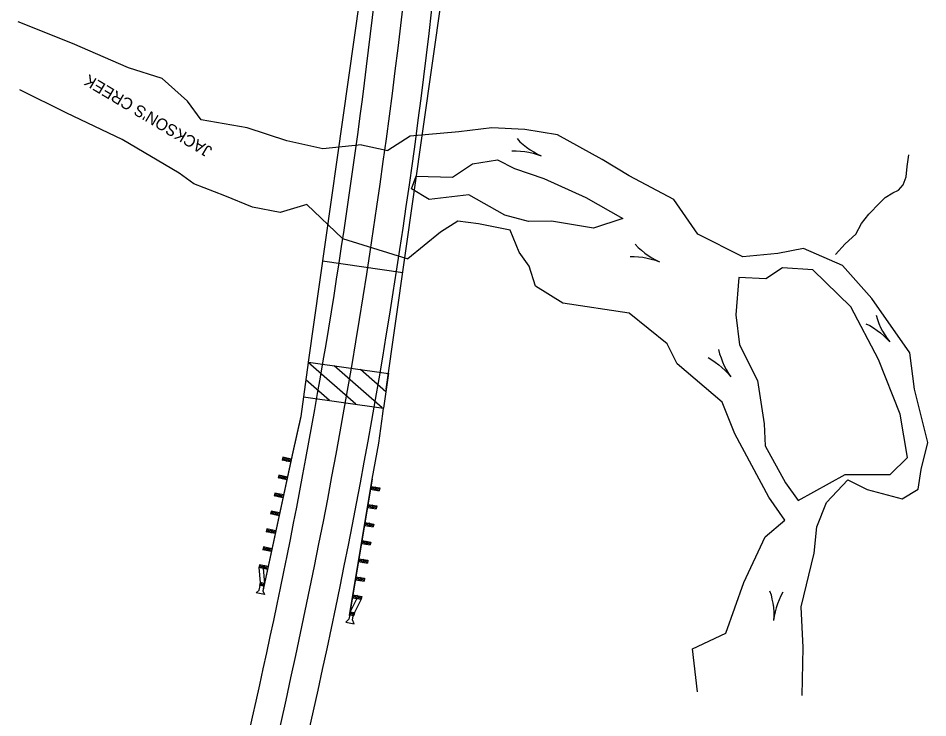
# Model space of a CAD drawing. Extents: x 1698609 to 1700392, y 707479 to 710040.
# Drawn here: x 1699277.7 to 1699590.3, y 708555.6 to 708796 of the extents above; entities that cross this region are included whole.
import ezdxf

# ---------------------------------------------------------------- set-up
doc = ezdxf.new("R2010")
doc.units = 0
for name, color, linetype in [('Default', 7, 'Continuous'), ('Exist Hydro Jurisdictional Stream or Body of Water', 7, 'Continuous'), ('Exist Hydro Jurisdictional Stream or Body of Water Text', 7, 'Continuous'), ('Exist Hydro Stream Flow Arrow CELL', 7, 'Continuous'), ('Exist Hydro Stream or Body of Water', 7, 'Continuous'), ('Prop Horizontal Alignment', 7, 'Continuous')]:
    doc.layers.add(name, color=color, linetype=linetype)

# ---------------------------------------------------------------- blocks, each defined once
blk = doc.blocks.new('EXIST HYDRO STREAM FLOW ARROW')
at = {"layer": 'Exist Hydro Stream Flow Arrow CELL'}
blk.add_line((0, 0), (0, 0), dxfattribs=at)
for points in [[(-0.1, 0.04575), (-0.07325, 0.03375), (-0.04475, 0.0245), (-0.0165, 0.01575), (0.01175, 0.0095), (0.041, 0.00475), (0.07075, 0.0015), (0.1, 0)], [(-0.1, -0.04575), (-0.07325, -0.03375), (-0.04475, -0.0245), (-0.0165, -0.01575), (0.01175, -0.0095), (0.041, -0.00475), (0.07075, -0.0015), (0.1, 0)]]:
    blk.add_lwpolyline(points, dxfattribs=at)

msp = doc.modelspace()

# ---------------------------------------------------------------- linework, layer by layer
at = {"layer": 'Default'}
for p, q in [((1699377.38, 708677.82), (1699397.03, 708816.44)), ((1699404.18, 708668.57), (1699424.59, 708812.53)), ((1699409.85, 708708.57), (1699382.3, 708712.47)), ((1699377.37, 708677.75), (1699375.7, 708665.94)), ((1699393.66, 708663.39), (1699377.36, 708677.67)), ((1699377.38, 708677.82), (1699404.94, 708673.92)), ((1699402.72, 708662.11), (1699386.21, 708676.57)), ((1699404.05, 708667.59), (1699395.26, 708675.29)), ((1699404.95, 708673.99), (1699403.26, 708662.03)), ((1699384.61, 708664.68), (1699376.52, 708671.76)), ((1699375.73, 708665.94), (1699374.79, 708659.14)), ((1699375.7, 708665.94), (1699403.26, 708662.03)), ((1699402.98, 708660.05), (1699403.26, 708662.03)), ((1699374.75, 708659.26), (1699372.04, 708647.01)), ((1699374.79, 708659.14), (1699372.08, 708646.9)), ((1699401.55, 708650.01), (1699402.98, 708660.05)), ((1699399.36, 708637.66), (1699401.55, 708650.01)), ((1699399.36, 708637.66), (1699401.55, 708650.01)), ((1699372.08, 708646.9), (1699361.75, 708599.17)), ((1699372.04, 708647.01), (1699362.19, 708601.31)), ((1699368.57, 708645.16), (1699368.36, 708644.18)), ((1699371.51, 708644.53), (1699368.57, 708645.16)), ((1699369.83, 708643.87), (1699368.57, 708645.16)), ((1699368.36, 708644.18), (1699370.04, 708644.85)), ((1699371.29, 708643.55), (1699368.36, 708644.18)), ((1699370.04, 708644.85), (1699369.83, 708643.87)), ((1699369.83, 708643.87), (1699371.51, 708644.53)), ((1699371.29, 708643.55), (1699369.83, 708643.87)), ((1699370.04, 708644.85), (1699371.29, 708643.55)), ((1699371.51, 708644.53), (1699371.29, 708643.55)), ((1699367.19, 708639.01), (1699366.98, 708638.04)), ((1699366.98, 708638.04), (1699368.69, 708638.69)), ((1699370.18, 708638.37), (1699367.19, 708639.01)), ((1699368.47, 708637.71), (1699367.19, 708639.01)), ((1699368.69, 708638.69), (1699368.47, 708637.71)), ((1699368.69, 708638.69), (1699369.97, 708637.39)), ((1699369.97, 708637.39), (1699366.98, 708638.04)), ((1699370.18, 708638.37), (1699368.47, 708637.71)), ((1699391.51, 708590.84), (1699399.36, 708637.66)), ((1699399.36, 708637.66), (1699391.63, 708591.55)), ((1699365.87, 708632.85), (1699365.66, 708631.87)), ((1699365.66, 708631.87), (1699367.36, 708632.53)), ((1699368.85, 708632.21), (1699365.87, 708632.85)), ((1699367.15, 708631.55), (1699365.87, 708632.85)), ((1699367.36, 708632.53), (1699367.15, 708631.55)), ((1699367.36, 708632.53), (1699368.64, 708631.23)), ((1699398.94, 708635.15), (1699398.77, 708634.17)), ((1699400.42, 708634.91), (1699398.77, 708634.17)), ((1699398.77, 708634.17), (1699401.73, 708633.67)), ((1699398.77, 708634.17), (1699400.25, 708633.92)), ((1699398.94, 708635.15), (1699401.9, 708634.66)), ((1699400.25, 708633.92), (1699398.94, 708635.15)), ((1699400.42, 708634.91), (1699400.25, 708633.92)), ((1699400.25, 708633.92), (1699401.9, 708634.66)), ((1699401.73, 708633.67), (1699400.42, 708634.91)), ((1699401.9, 708634.66), (1699401.73, 708633.67)), ((1699368.64, 708631.23), (1699365.66, 708631.87)), ((1699368.85, 708632.21), (1699367.15, 708631.55)), ((1699364.55, 708626.69), (1699364.34, 708625.71)), ((1699364.34, 708625.71), (1699366.04, 708626.37)), ((1699367.52, 708626.05), (1699364.55, 708626.69)), ((1699365.83, 708625.39), (1699364.55, 708626.69)), ((1699366.04, 708626.37), (1699365.83, 708625.39)), ((1699366.04, 708626.37), (1699367.31, 708625.07)), ((1699399.4, 708628.69), (1699397.73, 708627.95)), ((1699397.73, 708627.95), (1699400.74, 708627.45)), ((1699397.9, 708628.94), (1699400.91, 708628.43)), ((1699397.9, 708628.94), (1699399.24, 708627.7)), ((1699399.4, 708628.69), (1699399.24, 708627.7)), ((1699399.24, 708627.7), (1699400.91, 708628.43)), ((1699400.74, 708627.45), (1699399.4, 708628.69)), ((1699400.91, 708628.43), (1699400.74, 708627.45)), ((1699367.31, 708625.07), (1699364.34, 708625.71)), ((1699367.52, 708626.05), (1699365.83, 708625.39)), ((1699367.52, 708626.05), (1699367.31, 708625.07)), ((1699363.13, 708620.55), (1699362.92, 708619.57)), ((1699362.92, 708619.57), (1699364.66, 708620.22)), ((1699366.19, 708619.89), (1699363.13, 708620.55)), ((1699364.45, 708619.24), (1699363.13, 708620.55)), ((1699364.66, 708620.22), (1699364.45, 708619.24)), ((1699366.19, 708619.89), (1699364.45, 708619.24)), ((1699364.66, 708620.22), (1699365.98, 708618.91)), ((1699398.36, 708622.47), (1699396.69, 708621.74)), ((1699396.69, 708621.74), (1699399.7, 708621.23)), ((1699396.86, 708622.72), (1699399.86, 708622.22)), ((1699396.86, 708622.72), (1699398.19, 708621.49)), ((1699398.36, 708622.47), (1699398.19, 708621.49)), ((1699398.19, 708621.49), (1699399.86, 708622.22)), ((1699399.7, 708621.23), (1699398.36, 708622.47)), ((1699399.86, 708622.22), (1699399.7, 708621.23)), ((1699365.98, 708618.91), (1699362.92, 708619.57)), ((1699361.93, 708614.36), (1699361.72, 708613.38)), ((1699361.72, 708613.38), (1699363.4, 708614.05)), ((1699364.87, 708613.73), (1699361.93, 708614.36)), ((1699363.19, 708613.07), (1699361.93, 708614.36)), ((1699363.4, 708614.05), (1699363.19, 708613.07)), ((1699364.87, 708613.73), (1699363.19, 708613.07)), ((1699363.4, 708614.05), (1699364.65, 708612.75)), ((1699395.82, 708616.51), (1699395.65, 708615.52)), ((1699397.31, 708616.26), (1699395.65, 708615.52)), ((1699395.65, 708615.52), (1699398.64, 708615.02)), ((1699395.82, 708616.51), (1699398.81, 708616.01)), ((1699395.82, 708616.51), (1699397.15, 708615.27)), ((1699397.31, 708616.26), (1699397.15, 708615.27)), ((1699397.15, 708615.27), (1699398.81, 708616.01)), ((1699398.64, 708615.02), (1699397.31, 708616.26)), ((1699398.81, 708616.01), (1699398.64, 708615.02)), ((1699364.65, 708612.75), (1699361.72, 708613.38)), ((1699360.54, 708608.22), (1699360.33, 708607.24)), ((1699360.33, 708607.24), (1699362.04, 708607.89)), ((1699363.54, 708607.57), (1699360.54, 708608.22)), ((1699361.83, 708606.92), (1699360.54, 708608.22)), ((1699362.04, 708607.89), (1699361.83, 708606.92)), ((1699363.54, 708607.57), (1699361.83, 708606.92)), ((1699362.04, 708607.89), (1699363.33, 708606.59)), ((1699396.32, 708610.04), (1699394.61, 708609.31)), ((1699394.61, 708609.31), (1699397.7, 708608.79)), ((1699394.77, 708610.3), (1699397.87, 708609.78)), ((1699394.77, 708610.3), (1699396.16, 708609.05)), ((1699396.32, 708610.04), (1699396.16, 708609.05)), ((1699396.16, 708609.05), (1699397.87, 708609.78)), ((1699397.7, 708608.79), (1699396.32, 708610.04)), ((1699397.87, 708609.78), (1699397.7, 708608.79)), ((1699363.33, 708606.59), (1699360.33, 708607.24)), ((1699360.33, 708607.24), (1699360.83, 708602.12)), ((1699361.83, 708606.92), (1699362.29, 708601.8)), ((1699360.51, 708599.53), (1699360.91, 708601.53)), ((1699360.83, 708602.12), (1699360.62, 708601.14)), ((1699360.62, 708601.14), (1699362.29, 708601.8)), ((1699362.08, 708600.82), (1699360.62, 708601.14)), ((1699360.83, 708602.12), (1699360.72, 708601.63)), ((1699362.29, 708601.8), (1699360.83, 708602.12)), ((1699362.08, 708600.82), (1699360.83, 708602.12)), ((1699360.91, 708601.53), (1699361.51, 708601.42)), ((1699361.51, 708601.42), (1699362.11, 708601.3)), ((1699362.11, 708601.3), (1699361.71, 708599.29)), ((1699395.21, 708603.83), (1699393.57, 708603.09)), ((1699393.57, 708603.09), (1699396.53, 708602.6)), ((1699393.73, 708604.08), (1699396.69, 708603.59)), ((1699393.73, 708604.08), (1699395.05, 708602.85)), ((1699395.21, 708603.83), (1699395.05, 708602.85)), ((1699395.05, 708602.85), (1699396.69, 708603.59)), ((1699396.53, 708602.6), (1699395.21, 708603.83)), ((1699396.69, 708603.59), (1699396.53, 708602.6)), ((1699359.45, 708598.54), (1699360.51, 708599.53)), ((1699362.33, 708597.97), (1699359.45, 708598.54)), ((1699361.71, 708599.29), (1699362.33, 708597.97)), ((1699394.04, 708596.63), (1699391.72, 708592.05)), ((1699394.2, 708597.61), (1699392.53, 708596.88)), ((1699392.53, 708596.88), (1699395.55, 708596.37)), ((1699392.69, 708597.87), (1699395.71, 708597.36)), ((1699392.69, 708597.87), (1699394.04, 708596.63)), ((1699395.55, 708596.37), (1699393.19, 708591.8)), ((1699394.2, 708597.61), (1699394.04, 708596.63)), ((1699394.04, 708596.63), (1699395.71, 708597.36)), ((1699395.55, 708596.37), (1699394.2, 708597.61)), ((1699395.71, 708597.36), (1699395.55, 708596.37)), ((1699391.55, 708591.06), (1699393.19, 708591.8)), ((1699391.72, 708592.05), (1699393.19, 708591.8)), ((1699393.03, 708590.81), (1699391.72, 708592.05)), ((1699393.19, 708591.8), (1699393.03, 708590.81)), ((1699393.19, 708591.8), (1699393.11, 708591.31)), ((1699391.33, 708589.5), (1699390.26, 708588.5)), ((1699391.7, 708591.51), (1699391.33, 708589.5)), ((1699391.55, 708591.06), (1699393.03, 708590.81)), ((1699392.3, 708591.4), (1699391.7, 708591.51)), ((1699392.9, 708591.29), (1699392.3, 708591.4)), ((1699392.53, 708589.27), (1699392.9, 708591.29)), ((1699393.15, 708587.96), (1699392.53, 708589.27)), ((1699390.26, 708588.5), (1699393.15, 708587.96))]:
    msp.add_line(p, q, dxfattribs=at)
for centre, radius, start, end in [((1697124.94, 709062.69), 2310, 350.26654, 356.20849), ((1697132.82, 709061.2), 2282.04, 344.49766, 353.61848), ((1697124.94, 709062.69), 2310, 344.49666, 350.26654)]:
    msp.add_arc(centre, radius, start, end, dxfattribs=at)
at = {"layer": 'Exist Hydro Jurisdictional Stream or Body of Water'}
for p, q in [((1699395.69, 708752.5), (1699404.74, 708750.56)), ((1699412.8, 708737.33), (1699414.38, 708741.71)), ((1699389.13, 708720.33), (1699411.61, 708713.36)), ((1699525.28, 708706.88), (1699524.31, 708694.13)), ((1699541.4, 708636.34), (1699545.67, 708630.32))]:
    msp.add_line(p, q, dxfattribs=at)
for points in [[(1699395.69, 708752.5), (1699382.37, 708751.07), (1699369.98, 708753.84), (1699356.37, 708758.31), (1699340.59, 708761.05), (1699335.85, 708767.51), (1699327.2, 708775.23), (1699315.6, 708778.97), (1699296.29, 708787.35), (1699277.67, 708794.77)], [(1699389.13, 708720.33), (1699376.83, 708731.94), (1699367.73, 708729.25), (1699358.15, 708731.02), (1699348.73, 708735), (1699338.06, 708739.12), (1699332.93, 708742.73), (1699313.42, 708754.35), (1699294.36, 708763.36), (1699278.24, 708771.37)], [(1699547.13, 708563.35), (1699547.42, 708579.76), (1699546.74, 708593.74), (1699551.17, 708612.16), (1699552.12, 708621.29), (1699555.47, 708629.59), (1699562.79, 708637.43), (1699569.46, 708634.07), (1699581.43, 708630.92), (1699586.99, 708634.14), (1699587.99, 708640.93), (1699590.26, 708650.26), (1699585.71, 708668.59), (1699584.14, 708681.02), (1699571.05, 708699.72), (1699561, 708710.99), (1699547.59, 708716.92), (1699538.75, 708715.1), (1699526.67, 708714.06), (1699511.26, 708721.82), (1699503.01, 708733.73), (1699487.6, 708741.83), (1699478.34, 708747.45), (1699463.03, 708755.91), (1699451.77, 708757.79), (1699440.41, 708758.35), (1699429.1, 708756.97), (1699412.42, 708755.48), (1699404.74, 708750.56)], [(1699414.38, 708741.71), (1699426.92, 708741.38), (1699433.84, 708746.01), (1699442.35, 708747.34), (1699448.22, 708744.31), (1699458.31, 708740.9), (1699472.77, 708734.35), (1699485.49, 708727.18), (1699475.38, 708723.9), (1699460.94, 708726.27), (1699453.06, 708726.19), (1699444.88, 708728.31), (1699432.56, 708735.26), (1699418.89, 708733.7), (1699412.8, 708737.33)], [(1699511.06, 708564.57), (1699509.42, 708579.38), (1699520.83, 708584.67), (1699527.01, 708602.11), (1699534.34, 708617.81), (1699541.15, 708623.58), (1699535.64, 708631.45), (1699523.95, 708653.24), (1699519.62, 708664.12), (1699504.11, 708677.21), (1699500.74, 708684.08), (1699487.62, 708694.66), (1699464.84, 708698.13), (1699455.43, 708703.96), (1699453.21, 708710.76), (1699449.86, 708715.62), (1699446.69, 708723.16), (1699435.9, 708725.34), (1699428.73, 708726.26), (1699422.85, 708722.53), (1699411.61, 708713.36)], [(1699545.67, 708630.32), (1699561.82, 708639.24), (1699577.31, 708639.28), (1699583.26, 708645.04), (1699580.73, 708659.99), (1699573.36, 708678.78), (1699563.78, 708696.86), (1699550.72, 708709.59), (1699540.36, 708710.21), (1699534.63, 708706.4), (1699525.28, 708706.88)], [(1699524.31, 708694.13), (1699525.5, 708683.76), (1699531.73, 708671.5), (1699534.03, 708656.6), (1699534.42, 708649.03), (1699541.4, 708636.34)]]:
    msp.add_lwpolyline(points, dxfattribs=at)
at = {"layer": 'Exist Hydro Stream or Body of Water'}
msp.add_lwpolyline([(1699558.53, 708714.8), (1699561.81, 708718.44), (1699565.5, 708721.84), (1699567.45, 708725.44), (1699570.04, 708728.7), (1699573.76, 708732.6), (1699575.61, 708734.43), (1699578.27, 708735.95), (1699580.21, 708736.87), (1699581.85, 708738.74), (1699582.8, 708741.45), (1699583.18, 708744.99), (1699583.73, 708749.07)], dxfattribs=at)
at = {"layer": 'Prop Horizontal Alignment'}
msp.add_arc((1697124.94, 709062.69), 2300, 343.70663, 356.20849, dxfattribs=at)

# ---------------------------------------------------------------- block references
at = {"layer": 'Exist Hydro Stream Flow Arrow CELL'}
for p, xscale, yscale, rotation in [((1699452.83, 708750.6), 49.99999999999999, 50, -22.58903539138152), ((1699493.42, 708714.27), 50, 50, -23.04994341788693), ((1699573.97, 708688.62), 50.00000000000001, 49.99999999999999, -50.384582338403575), ((1699519.56, 708676.75), 50, 50, -53.11082354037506), ((1699537.73, 708594.09), 50, 50.00000000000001, -95.16364271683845)]:
    msp.add_blockref('EXIST HYDRO STREAM FLOW ARROW', p, dxfattribs=dict(at, xscale=xscale, yscale=yscale, rotation=rotation))

# ---------------------------------------------------------------- texts
at = {"layer": 'Exist Hydro Jurisdictional Stream or Body of Water Text'}
msp.add_text("JACKSON'S CREEK", height=4, rotation=149.2295, dxfattribs=at).set_placement((1699344.68, 708751.37))

doc.saveas('drawing.dxf')
